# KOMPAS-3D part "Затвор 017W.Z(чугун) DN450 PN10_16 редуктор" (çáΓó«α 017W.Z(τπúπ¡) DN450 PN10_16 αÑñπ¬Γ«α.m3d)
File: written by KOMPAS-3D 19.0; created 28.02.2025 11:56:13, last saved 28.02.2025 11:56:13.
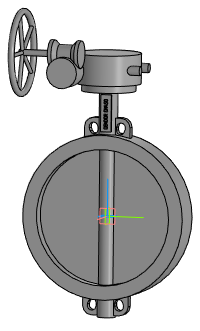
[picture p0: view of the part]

Document properties: Автор: Евгений; Полное имя файла: Затвор 017W.Z(чугун) DN450 PN10_16 редуктор.a3d

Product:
- Part/product: Затвор 017W.Z(чугун) DN450 PN10_16 редуктор
    Масса: 146.259

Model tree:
1. Операция без истории:1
